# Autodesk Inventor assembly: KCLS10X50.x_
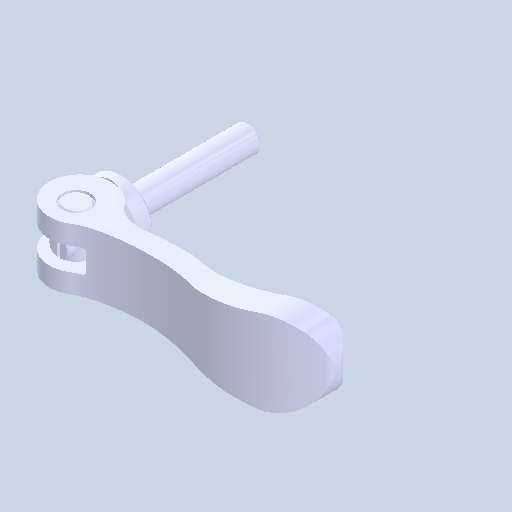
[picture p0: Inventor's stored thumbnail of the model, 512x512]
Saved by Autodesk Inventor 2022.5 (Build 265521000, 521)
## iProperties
Created: 2024-08
Part Number: KCLS10X50.x_
Document SubType Name: Assembly
Designer: ImaoCorp
Author: ImaoCorp
Sending System: SOLIDWORKS 2022-2022290
MC: AMD64
MC_MODEL: Intel64 Family 6 Model 60 Stepping 3, GenuineIntel
OS: Windows_NT
FRU: Parasolid Version 33.1, build 260,  4-25-2022
FORMAT: text
GUISE: transmit
KEY: FILEKCLS10X50.x_t
DATE: Thu Aug 29 10:55:24 2024
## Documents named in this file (5)
- Y:\5.更新分\2024年対応\1001_KCL\データ\kcls10x50\KCLS10X50.x_.iam
- Y:\5.更新分\2024年対応\1001_KCL\データ\kcls10x50\KCLS10X50_01.ipt
- Y:\5.更新分\2024年対応\1001_KCL\データ\kcls10x50\KCLS10X50_02.ipt
- Y:\5.更新分\2024年対応\1001_KCL\データ\kcls10x50\KCLS10X50_03.ipt
- Y:\5.更新分\2024年対応\1001_KCL\データ\kcls10x50\KCLS10X50_04.ipt
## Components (4 placed, 4 different names)
1. KCLS10X50_01
2. KCLS10X50_02
3. KCLS10X50_03
4. KCLS10X50_04
